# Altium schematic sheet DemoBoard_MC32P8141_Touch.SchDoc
size A4
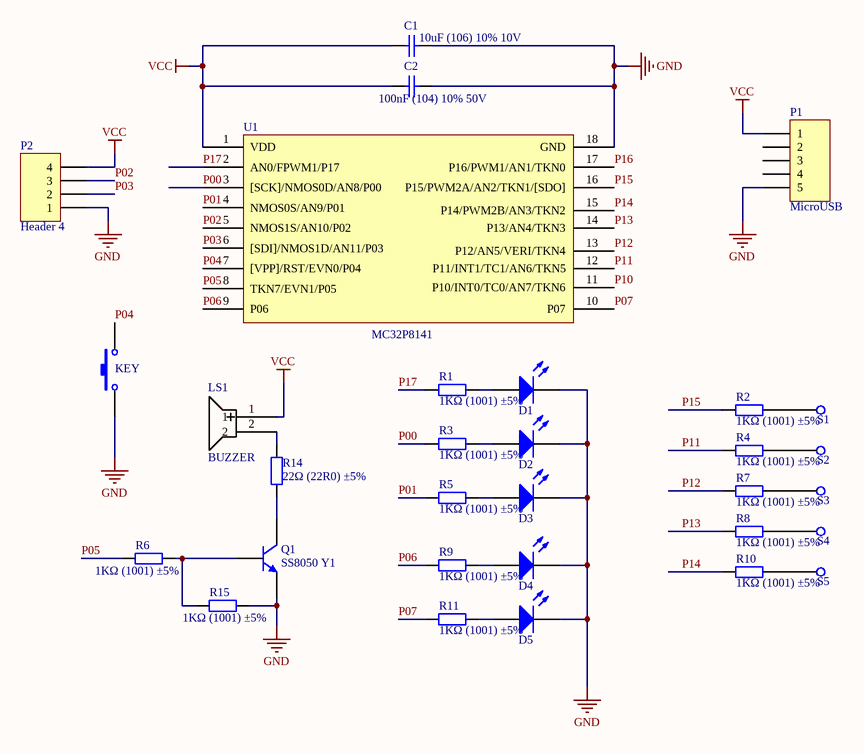
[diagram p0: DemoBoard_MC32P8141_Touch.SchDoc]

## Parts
C1  10uF (106) 10% 10V  [0603_C]
C2  100nF (104) 10% 50V  [0603_C]
D1  蓝灯 0805  [0805_drill_LED]  (value not drawn)
D2  蓝灯 0805  [0805_drill_LED]  (value not drawn)
D3  蓝灯 0805  [0805_drill_LED]  (value not drawn)
D4  蓝灯 0805  [0805_drill_LED]  (value not drawn)
D5  蓝灯 0805  [0805_drill_LED]  (value not drawn)
KEY  (no value)  [KEY_6*6]
LS1  BUZZER  [BZ]
P1  MicroUSB  [MICRO-USB-1]
P2  Header 4  [HDR1X4]
Q1  SS8050 Y1  [SOT-23(SOT-23-3)]
R1  1KΩ (1001) ±5%  [0603_R]
R2  1KΩ (1001) ±5%  [0603_R]
R3  1KΩ (1001) ±5%  [0603_R]
R4  1KΩ (1001) ±5%  [0603_R]
R5  1KΩ (1001) ±5%  [0603_R]
R6  1KΩ (1001) ±5%  [0603_R]
R7  1KΩ (1001) ±5%  [0603_R]
R8  1KΩ (1001) ±5%  [0603_R]
R9  1KΩ (1001) ±5%  [0603_R]
R10  1KΩ (1001) ±5%  [0603_R]
R11  1KΩ (1001) ±5%  [0603_R]
R14  22Ω (22R0) ±5%  [0603_R]
R15  1KΩ (1001) ±5%  [0603_R]
S1  TK_Button  [TK]  (value not drawn)
S2  TK_Button  [TK]  (value not drawn)
S3  TK_Button  [TK]  (value not drawn)
S4  TK_Button  [TK]  (value not drawn)
S5  TK_Button  [TK]  (value not drawn)
U1  MC32P8141  [SOP18]

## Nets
GND: C1.2 C2.2 D1.K D2.K D3.K D4.K D5.K KEY.1 P1.5 P2.1 Q1.2(E) R15.2 U1.18(GND)
VCC: C1.1 C2.1 LS1.1 P1.1 P2.4 U1.1(VDD)
P00: R3.1 U1.3([SCK]/NMOS0D/AN8/P00)
P01: R5.1 U1.4(NMOS0S/AN9/P01)
P02: P2.3 U1.5(NMOS1S/AN10/P02)
P03: P2.2 U1.6([SDI]/NMOS1D/AN11/P03)
P04: KEY.2 U1.7([VPP]/RST/EVN0/P04)
P05: R6.1 U1.8(TKN7/EVN1/P05)
P06: R9.1 U1.9(P06)
P07: R11.1 U1.10(P07)
P10: U1.11(P10/INT0/TC0/AN7/TKN6)
P11: R4.1 U1.12(P11/INT1/TC1/AN6/TKN5)
P12: R7.1 U1.13(P12/AN5/VERI/TKN4)
P13: R8.1 U1.14(P13/AN4/TKN3)
P14: R10.1 U1.15(P14/PWM2B/AN3/TKN2)
P15: R2.1 U1.16(P15/PWM2A/AN2/TKN1/[SDO])
P16: U1.17(P16/PWM1/AN1/TKN0)
P17: R1.1 U1.2(AN0/FPWM1/P17)
NetD1_A: D1.A R1.2
NetD2_A: D2.A R3.2
NetD3_A: D3.A R5.2
NetD4_A: D4.A R9.2
NetD5_A: D5.A R11.2
NetLS1_2: LS1.2 R14.2
NetQ1_1: Q1.1(B) R6.2 R15.1
NetQ1_3: Q1.3(C) R14.1
NetR2_2: R2.2 S1.1
NetR4_2: R4.2 S2.1
NetR7_2: R7.2 S3.1
NetR8_2: R8.2 S4.1
NetR10_2: R10.2 S5.1

Not connected (* = marked no-connect by the designer): P1 2 3 4

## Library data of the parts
C1 = 0603 1: 贴片电容
C2 = 0603 10: 贴片电容
D1-D5 = 0: 发光二极管
KEY = SW-PB: Switch
LS1 = BUZZER: GSD12810YB-3V2400
P1 = Header 5: Header, 5-Pin
P2 = Header 4: Header, 4-Pin
Q1 = SOT-23 SS: 三极管; ComponentLink1Descrip: 供应商链接
R1-R5 R7-R11 = 0603 1KΩ (100: 贴片电阻
R6 R14 R15 = 0603: 贴片电阻; ComponentLink1Descrip: 供应商链接
U1 = SOP18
